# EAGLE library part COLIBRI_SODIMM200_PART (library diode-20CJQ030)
TORADEX's Colibri So-Dimm 200 ModuleCDRH2D18/HP Intel XScale®Based SODIMMSizedComputer Colibri is a SODIMMsized computer module based on the new Intel XScale PXA270processor. It runs at up to 520 MHz and consumes as little as 800 mW. The power consumption is optimised using the new Wireless Intel Speedstep Technology. The module delivers state of the art technology, targeting low power systems that still require high CPU performance. It also offers all the interfaces needed in a modern embedded device. The module provides glueless connectivity to passive and active LCDs with resolutions of up to 800x600, as well as 4-wire resistive touch screens. An integrated 16 bit stereo codec allows Colibri to play and recordsound. Colibri can directly connect to a CCDcamera sensor, or take advantage of the new Intel Mobile Scalable Link that offers transfer speeds of upto416Mbps. In addition Colibri offers a 100 MBit Ethernet as well as USB host and USB device functionality. Flexibility andSecondSource Colibri can be scaled to meet specific cost requirements: Assembly options are available for Ethernet, Audio Codec, FLASHsize, RAMsize and CPUspeed. The entire 32 bit wide CPU bus is available for custom extensions, such as special interfaces for high bandwidth applications. Colibri Modules can be used as a replacement for Keith &Koep's Trizeps III / IV family of modules. Colibri comes with a pre-installedoperating systemand state of the art development tools that allow an easy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
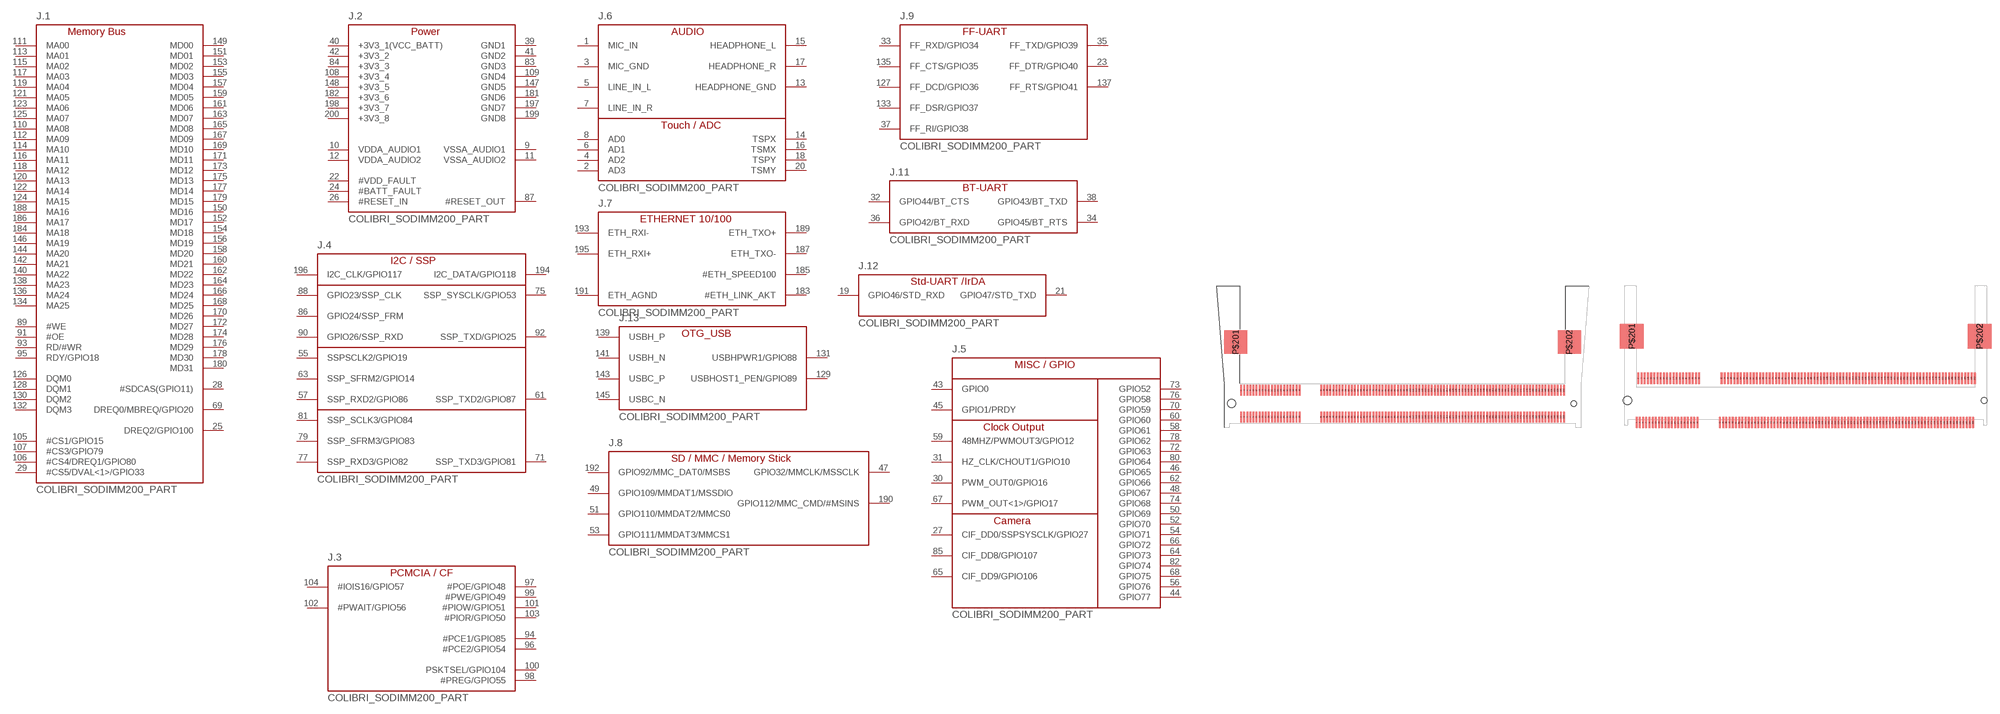
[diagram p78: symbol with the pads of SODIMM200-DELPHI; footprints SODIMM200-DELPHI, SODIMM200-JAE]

Designator prefix J; gates .2=COLIBRI_POWER .6=COLIBRI_AUDIO_TOUCH_ADC .7=COLIBRI_ETHERNET .8=COLIBRI_SD_MMC .11=COLIBRI_BT_UART .12=COLIBRI_STD_UART .3=COLIBRI_PCMCIA .1=COLIBRI_MEM .13=COLIBRI_USB .5=COLIBRI_MISC .9=COLIBRI_FF_UART .4=COLIBRI_I2C_SSP

## COLIBRI_SODIMM200_PART-DELPHI  [SODIMM200-DELPHI]
1  .6:MIC_IN  pas
2  .6:AD3  pas
3  .6:MIC_GND  pas
4  .6:AD2  pas
5  .6:LINE_IN_L  pas
6  .6:AD1  pas
7  .6:LINE_IN_R  pas
8  .6:AD0  pas
9  .2:VSSA_AUDIO1  pas
10  .2:VDDA_AUDIO1  pas
11  .2:VSSA_AUDIO2  pas
12  .2:VDDA_AUDIO2  pas
13  .6:HEADPHONE_GND  pas
14  .6:TSPX  pas
15  .6:HEADPHONE_L  pas
16  .6:TSMX  pas
17  .6:HEADPHONE_R  pas
18  .6:TSPY  pas
19  .12:GPIO46/STD_RXD  pas
20  .6:TSMY  pas
21  .12:GPIO47/STD_TXD  pas
22  .2:#VDD_FAULT  pas
23  .9:FF_DTR/GPIO40  pas
24  .2:#BATT_FAULT  pas
25  .1:DREQ2/GPIO100  pas
26  .2:#RESET_IN  pas
27  .5:CIF_DD0/SSPSYSCLK/GPIO27  pas
28  .1:#SDCAS(GPIO11)  pas
29  .1:#CS5/DVAL<1>/GPIO33  pas
30  .5:PWM_OUT0/GPIO16  pas
31  .5:HZ_CLK/CHOUT1/GPIO10  pas
32  .11:GPIO44/BT_CTS  pas
33  .9:FF_RXD/GPIO34  pas
34  .11:GPIO45/BT_RTS  pas
35  .9:FF_TXD/GPIO39  pas
36  .11:GPIO42/BT_RXD  pas
37  .9:FF_RI/GPIO38  pas
38  .11:GPIO43/BT_TXD  pas
39  .2:GND1  pas
40  .2:+3V3_1(VCC_BATT)  pas
41  .2:GND2  pas
42  .2:+3V3_2  pas
43  .5:GPIO0  pas
44  .5:GPIO77  pas
45  .5:GPIO1/PRDY  pas
46  .5:GPIO65  pas
47  .8:GPIO32/MMCLK/MSSCLK  pas
48  .5:GPIO67  pas
49  .8:GPIO109/MMDAT1/MSSDIO  pas
50  .5:GPIO69  pas
51  .8:GPIO110/MMDAT2/MMCS0  pas
52  .5:GPIO70  pas
53  .8:GPIO111/MMDAT3/MMCS1  pas
54  .5:GPIO71  pas
55  .4:SSPSCLK2/GPIO19  pas
56  .5:GPIO76  pas
57  .4:SSP_RXD2/GPIO86  pas
58  .5:GPIO61  pas
59  .5:48MHZ/PWMOUT3/GPIO12  pas
60  .5:GPIO60  pas
61  .4:SSP_TXD2/GPIO87  pas
62  .5:GPIO66  pas
63  .4:SSP_SFRM2/GPIO14  pas
64  .5:GPIO73  pas
65  .5:CIF_DD9/GPIO106  pas
66  .5:GPIO72  pas
67  .5:PWM_OUT<1>/GPIO17  pas
68  .5:GPIO75  pas
69  .1:DREQ0/MBREQ/GPIO20  pas
70  .5:GPIO59  pas
71  .4:SSP_TXD3/GPIO81  pas
72  .5:GPIO63  pas
73  .5:GPIO52  pas
74  .5:GPIO68  pas
75  .4:SSP_SYSCLK/GPIO53  pas
76  .5:GPIO58  pas
77  .4:SSP_RXD3/GPIO82  pas
78  .5:GPIO62  pas
79  .4:SSP_SFRM3/GPIO83  pas
80  .5:GPIO64  pas
81  .4:SSP_SCLK3/GPIO84  pas
82  .5:GPIO74  pas
83  .2:GND3  pas
84  .2:+3V3_3  pas
85  .5:CIF_DD8/GPIO107  pas
86  .4:GPIO24/SSP_FRM  pas
87  .2:#RESET_OUT  pas
88  .4:GPIO23/SSP_CLK  pas
89  .1:#WE  pas
90  .4:GPIO26/SSP_RXD  pas
91  .1:#OE  pas
92  .4:SSP_TXD/GPIO25  pas
93  .1:RD/#WR  pas
94  .3:#PCE1/GPIO85  pas
95  .1:RDY/GPIO18  pas
96  .3:#PCE2/GPIO54  pas
97  .3:#POE/GPIO48  pas
98  .3:#PREG/GPIO55  pas
99  .3:#PWE/GPIO49  pas
100  .3:PSKTSEL/GPIO104  pas
101  .3:#PIOW/GPIO51  pas
102  .3:#PWAIT/GPIO56  pas
103  .3:#PIOR/GPIO50  pas
104  .3:#IOIS16/GPIO57  pas
105  .1:#CS1/GPIO15  pas
106  .1:#CS4/DREQ1/GPIO80  pas
107  .1:#CS3/GPIO79  pas
108  .2:+3V3_4  pas
109  .2:GND4  pas
110  .1:MA08  pas
111  .1:MA00  pas
112  .1:MA09  pas
113  .1:MA01  pas
114  .1:MA10  pas
115  .1:MA02  pas
116  .1:MA11  pas
117  .1:MA03  pas
118  .1:MA12  pas
119  .1:MA04  pas
120  .1:MA13  pas
121  .1:MA05  pas
122  .1:MA14  pas
123  .1:MA06  pas
124  .1:MA15  pas
125  .1:MA07  pas
126  .1:DQM0  pas
127  .9:FF_DCD/GPIO36  pas
128  .1:DQM1  pas
129  .13:USBHOST1_PEN/GPIO89  pas
130  .1:DQM2  pas
131  .13:USBHPWR1/GPIO88  pas
132  .1:DQM3  pas
133  .9:FF_DSR/GPIO37  pas
134  .1:MA25  pas
135  .9:FF_CTS/GPIO35  pas
136  .1:MA24  pas
137  .9:FF_RTS/GPIO41  pas
138  .1:MA23  pas
139  .13:USBH_P  pas
140  .1:MA22  pas
141  .13:USBH_N  pas
142  .1:MA21  pas
143  .13:USBC_P  pas
144  .1:MA20  pas
145  .13:USBC_N  pas
146  .1:MA19  pas
147  .2:GND5  pas
148  .2:+3V3_5  pas
149  .1:MD00  pas
150  .1:MD16  pas
151  .1:MD01  pas
152  .1:MD17  pas
153  .1:MD02  pas
154  .1:MD18  pas
155  .1:MD03  pas
156  .1:MD19  pas
157  .1:MD04  pas
158  .1:MD20  pas
159  .1:MD05  pas
160  .1:MD21  pas
161  .1:MD06  pas
162  .1:MD22  pas
163  .1:MD07  pas
164  .1:MD23  pas
165  .1:MD08  pas
166  .1:MD24  pas
167  .1:MD09  pas
168  .1:MD25  pas
169  .1:MD10  pas
170  .1:MD26  pas
171  .1:MD11  pas
172  .1:MD27  pas
173  .1:MD12  pas
174  .1:MD28  pas
175  .1:MD13  pas
176  .1:MD29  pas
177  .1:MD14  pas
178  .1:MD30  pas
179  .1:MD15  pas
180  .1:MD31  pas
181  .2:GND6  pas
182  .2:+3V3_6  pas
183  .7:#ETH_LINK_AKT  pas
184  .1:MA18  pas
185  .7:#ETH_SPEED100  pas
186  .1:MA17  pas
187  .7:ETH_TXO-  pas
188  .1:MA16  pas
189  .7:ETH_TXO+  pas
190  .8:GPIO112/MMC_CMD/#MSINS  pas
191  .7:ETH_AGND  pas
192  .8:GPIO92/MMC_DAT0/MSBS  pas
193  .7:ETH_RXI-  pas
194  .4:I2C_DATA/GPIO118  pas
195  .7:ETH_RXI+  pas
196  .4:I2C_CLK/GPIO117  pas
197  .2:GND7  pas
198  .2:+3V3_7  pas
199  .2:GND8  pas
200  .2:+3V3_8  pas

## COLIBRI_SODIMM200_PART-JAE  [SODIMM200-JAE]
Pads as for SODIMM200-DELPHI

## Footprint SODIMM200-DELPHI (pad centres in mm)
smd 0.36 x 2.1: 1 -31.51,-2.6; 2 -31.5,2.6; 3 -30.91,-2.6; 4 -30.9,2.6; 5 -30.31,-2.6; 6 -30.3,2.6; 7 -29.71,-2.6; 8 -29.7,2.6; 9 -29.11,-2.6; 10 -29.1,2.6; 11 -28.51,-2.6; 12 -28.5,2.6; 13 -27.91,-2.6; 14 -27.9,2.6; 15 -27.31,-2.6; 16 -27.3,2.6; 17 -26.71,-2.6; 18 -26.7,2.6; 19 -26.11,-2.6; 20 -26.1,2.6; 21 -25.51,-2.6; 22 -25.5,2.6; 23 -24.91,-2.6; 24 -24.9,2.6; 25 -24.31,-2.6; 26 -24.3,2.6; 27 -23.71,-2.6; 28 -23.7,2.6; 29 -23.11,-2.6; 30 -23.1,2.6; 31 -22.51,-2.6; 32 -22.5,2.6; 33 -21.91,-2.6; 34 -21.9,2.6; 35 -21.31,-2.6; 36 -21.3,2.6; 37 -20.71,-2.6; 38 -20.7,2.6; 39 -20.11,-2.6; 40 -20.1,2.6; 41 -15.9,-2.6; 42 -15.9,2.6; 43 -15.3,-2.6; 44 -15.3,2.6; 45 -14.7,-2.6; 46 -14.7,2.6; 47 -14.1,-2.6; 48 -14.1,2.6; 49 -13.5,-2.6; 50 -13.5,2.6; 51 -12.9,-2.6; 52 -12.9,2.6; 53 -12.3,-2.6; 54 -12.3,2.6; 55 -11.7,-2.6; 56 -11.7,2.6; 57 -11.1,-2.6; 58 -11.1,2.6; 59 -10.5,-2.6; 60 -10.5,2.6; 61 -9.9,-2.6; 62 -9.9,2.6; 63 -9.3,-2.6; 64 -9.3,2.6; 65 -8.7,-2.6; 66 -8.7,2.6; 67 -8.1,-2.6; 68 -8.1,2.6; 69 -7.5,-2.6; 70 -7.5,2.6; 71 -6.9,-2.6; 72 -6.9,2.6; 73 -6.3,-2.6; 74 -6.3,2.6; 75 -5.7,-2.6; 76 -5.7,2.6; 77 -5.1,-2.6; 78 -5.1,2.6; 79 -4.5,-2.6; 80 -4.5,2.6; 81 -3.9,-2.6; 82 -3.9,2.6; 83 -3.3,-2.6; 84 -3.3,2.6; 85 -2.7,-2.6; 86 -2.7,2.6; 87 -2.1,-2.6; 88 -2.1,2.6; 89 -1.5,-2.6; 90 -1.5,2.6; 91 -0.9,-2.6; 92 -0.9,2.6; 93 -0.3,-2.6; 94 -0.3,2.6; 95 0.3,-2.6; 96 0.3,2.6; 97 0.9,-2.6; 98 0.9,2.6; 99 1.5,-2.6; 100 1.5,2.6; 101 2.1,-2.6; 102 2.1,2.6; 103 2.7,-2.6; 104 2.7,2.6; 105 3.3,-2.6; 106 3.3,2.6; 107 3.9,-2.6; 108 3.9,2.6; 109 4.5,-2.6; 110 4.5,2.6; 111 5.1,-2.6; 112 5.1,2.6; 113 5.7,-2.6; 114 5.7,2.6; 115 6.3,-2.6; 116 6.3,2.6; 117 6.9,-2.6; 118 6.9,2.6; 119 7.5,-2.6; 120 7.5,2.6; 121 8.1,-2.6; 122 8.1,2.6; 123 8.7,-2.6; 124 8.7,2.6; 125 9.3,-2.6; 126 9.3,2.6; 127 9.9,-2.6; 128 9.9,2.6; 129 10.5,-2.6; 130 10.5,2.6; 131 11.1,-2.6; 132 11.1,2.6; 133 11.7,-2.6; 134 11.7,2.6; 135 12.3,-2.6; 136 12.3,2.6; 137 12.9,-2.6; 138 12.9,2.6; 139 13.5,-2.6; 140 13.5,2.6; 141 14.1,-2.6; 142 14.1,2.6; 143 14.7,-2.6; 144 14.7,2.6; 145 15.3,-2.6; 146 15.3,2.6; 147 15.9,-2.6; 148 15.9,2.6; 149 16.5,-2.6; 150 16.5,2.6; 151 17.1,-2.6; 152 17.1,2.6; 153 17.7,-2.6; 154 17.7,2.6; 155 18.3,-2.6; 156 18.3,2.6; 157 18.9,-2.6; 158 18.9,2.6; 159 19.5,-2.6; 160 19.5,2.6; 161 20.1,-2.6; 162 20.1,2.6; 163 20.7,-2.6; 164 20.7,2.6; 165 21.3,-2.6; 166 21.3,2.6; 167 21.9,-2.6; 168 21.9,2.6; 169 22.5,-2.6; 170 22.5,2.6; 171 23.1,-2.6; 172 23.1,2.6; 173 23.7,-2.6; 174 23.7,2.6; 175 24.3,-2.6; 176 24.3,2.6; 177 24.9,-2.6; 178 24.9,2.6; 179 25.5,-2.6; 180 25.5,2.6; 181 26.1,-2.6; 182 26.1,2.6; 183 26.7,-2.6; 184 26.7,2.6; 185 27.3,-2.6; 186 27.3,2.6; 187 27.9,-2.6; 188 27.9,2.6; 189 28.5,-2.6; 190 28.5,2.6; 191 29.1,-2.6; 192 29.1,2.6; 193 29.7,-2.6; 194 29.7,2.6; 195 30.3,-2.6; 196 30.3,2.6; 197 30.9,-2.6; 198 30.9,2.6; 199 31.5,-2.6; 200 31.5,2.6
smd 4.5 x 4.6: P$201 -32.55,12; P$202 32.55,12
hole 1.1 at 33.4,0
hole 1.6 at -33.4,0

## Footprint SODIMM200-JAE (pad centres in mm)
JAE-Connector So-Dimm 200 Connector MM50 - 200B* - *
smd 0.36 x 2.1: 1 -31.65,-4.15; 2 -31.34,4.15; 3 -31.05,-4.15; 4 -30.74,4.15; 5 -30.45,-4.15; 6 -30.14,4.15; 7 -29.85,-4.15; 8 -29.54,4.15; 9 -29.25,-4.15; 10 -28.94,4.15; 11 -28.65,-4.15; 12 -28.34,4.15; 13 -28.05,-4.15; 14 -27.74,4.15; 15 -27.45,-4.15; 16 -27.14,4.15; 17 -26.85,-4.15; 18 -26.54,4.15; 19 -26.25,-4.15; 20 -25.94,4.15; 21 -25.65,-4.15; 22 -25.34,4.15; 23 -25.05,-4.15; 24 -24.74,4.15; 25 -24.45,-4.15; 26 -24.14,4.15; 27 -23.85,-4.15; 28 -23.54,4.15; 29 -23.25,-4.15; 30 -22.94,4.15; 31 -22.65,-4.15; 32 -22.34,4.15; 33 -22.05,-4.15; 34 -21.74,4.15; 35 -21.45,-4.15; 36 -21.14,4.15; 37 -20.85,-4.15; 38 -20.54,4.15; 39 -20.25,-4.15; 40 -19.94,4.15; 41 -16.04,-4.15; 42 -15.74,4.15; 43 -15.45,-4.15; 44 -15.14,4.15; 45 -14.85,-4.15; 46 -14.54,4.15; 47 -14.25,-4.15; 48 -13.94,4.15; 49 -13.65,-4.15; 50 -13.34,4.15; 51 -13.05,-4.15; 52 -12.74,4.15; 53 -12.45,-4.15; 54 -12.14,4.15; 55 -11.85,-4.15; 56 -11.54,4.15; 57 -11.25,-4.15; 58 -10.94,4.15; 59 -10.65,-4.15; 60 -10.34,4.15; 61 -10.05,-4.15; 62 -9.74,4.15; 63 -9.45,-4.15; 64 -9.14,4.15; 65 -8.85,-4.15; 66 -8.54,4.15; 67 -8.25,-4.15; 68 -7.94,4.15; 69 -7.65,-4.15; 70 -7.34,4.15; 71 -7.05,-4.15; 72 -6.74,4.15; 73 -6.45,-4.15; 74 -6.14,4.15; 75 -5.85,-4.15; 76 -5.54,4.15; 77 -5.25,-4.15; 78 -4.94,4.15; 79 -4.65,-4.15; 80 -4.34,4.15; 81 -4.05,-4.15; 82 -3.74,4.15; 83 -3.45,-4.15; 84 -3.14,4.15; 85 -2.85,-4.15; 86 -2.54,4.15; 87 -2.25,-4.15; 88 -1.94,4.15; 89 -1.65,-4.15; 90 -1.34,4.15; 91 -1.05,-4.15; 92 -0.74,4.15; 93 -0.45,-4.15; 94 -0.14,4.15; 95 0.15,-4.15; 96 0.46,4.15; 97 0.75,-4.15; 98 1.06,4.15; 99 1.35,-4.15; 100 1.66,4.15; 101 1.95,-4.15; 102 2.26,4.15; 103 2.55,-4.15; 104 2.86,4.15; 105 3.15,-4.15; 106 3.46,4.15; 107 3.75,-4.15; 108 4.06,4.15; 109 4.35,-4.15; 110 4.66,4.15; 111 4.95,-4.15; 112 5.26,4.15; 113 5.55,-4.15; 114 5.86,4.15; 115 6.15,-4.15; 116 6.46,4.15; 117 6.75,-4.15; 118 7.06,4.15; 119 7.35,-4.15; 120 7.66,4.15; 121 7.95,-4.15; 122 8.26,4.15; 123 8.55,-4.15; 124 8.86,4.15; 125 9.15,-4.15; 126 9.46,4.15; 127 9.75,-4.15; 128 10.06,4.15; 129 10.35,-4.15; 130 10.66,4.15; 131 10.95,-4.15; 132 11.26,4.15; 133 11.55,-4.15; 134 11.86,4.15; 135 12.15,-4.15; 136 12.46,4.15; 137 12.75,-4.15; 138 13.06,4.15; 139 13.35,-4.15; 140 13.66,4.15; 141 13.95,-4.15; 142 14.26,4.15; 143 14.55,-4.15; 144 14.86,4.15; 145 15.15,-4.15; 146 15.46,4.15; 147 15.75,-4.15; 148 16.06,4.15; 149 16.35,-4.15; 150 16.66,4.15; 151 16.95,-4.15; 152 17.26,4.15; 153 17.55,-4.15; 154 17.86,4.15; 155 18.15,-4.15; 156 18.46,4.15; 157 18.75,-4.15; 158 19.06,4.15; 159 19.35,-4.15; 160 19.66,4.15; 161 19.95,-4.15; 162 20.26,4.15; 163 20.55,-4.15; 164 20.86,4.15; 165 21.15,-4.15; 166 21.46,4.15; 167 21.75,-4.15; 168 22.06,4.15; 169 22.35,-4.15; 170 22.66,4.15; 171 22.95,-4.15; 172 23.26,4.15; 173 23.55,-4.15; 174 23.86,4.15; 175 24.15,-4.15; 176 24.46,4.15; 177 24.75,-4.15; 178 25.06,4.15; 179 25.35,-4.15; 180 25.66,4.15; 181 25.95,-4.15; 182 26.26,4.15; 183 26.55,-4.15; 184 26.86,4.15; 185 27.15,-4.15; 186 27.46,4.15; 187 27.75,-4.15; 188 28.06,4.15; 189 28.35,-4.15; 190 28.66,4.15; 191 28.95,-4.15; 192 29.26,4.15; 193 29.55,-4.15; 194 29.86,4.15; 195 30.15,-4.15; 196 30.46,4.15; 197 30.75,-4.15; 198 31.06,4.15; 199 31.35,-4.15; 200 31.66,4.15
smd 4.5 x 4.6: P$201 -32.55,12; P$202 32.55,12
hole 1.6 at -33.4,0
hole 1.1 at 33.4,0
